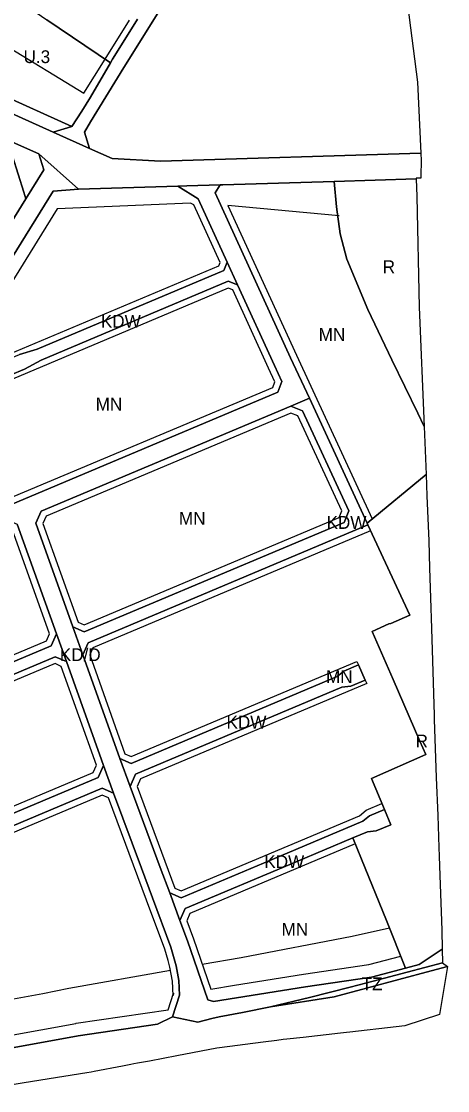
# Model space of a CAD drawing. Extents: x 7438199 to 7440548, y 5549253 to 5551017.
# Drawn here: x 7440215 to 7440548, y 5549426 to 5550261 of the extents above; entities that cross this region are included whole.
import ezdxf

# ---------------------------------------------------------------- set-up
doc = ezdxf.new("R2010")
doc.units = 0
for name, color, linetype in [('linie_rozgraniczajace', 7, 'Continuous'), ('linie_zabudowy_nieprzekraczalne', 7, 'Continuous'), ('oznaczenia_przeznaczen', 7, 'Continuous')]:
    doc.layers.add(name, color=color, linetype=linetype)

msp = doc.modelspace()

# ---------------------------------------------------------------- linework, layer by layer
at = {"layer": 'linie_rozgraniczajace'}
for points in [[(7440264.09, 5550174.87), (7440268.9, 5550182.89), (7440294.89, 5550225.52), (7440333.29, 5550286.98), (7440363.71, 5550335.92), (7440419.81, 5550425.76), (7440445, 5550466.09), (7440446.93, 5550470.08), (7440464.51, 5550499.53), (7440473.34, 5550465.22), (7440474.91, 5550458.79), (7440492.18, 5550389.39), (7440494, 5550382.09), (7440512.2, 5550309.41), (7440524.54, 5550213.92), (7440527.09, 5550158.4), (7440323.7, 5550152.27), (7440285.69, 5550154.28), (7440268.06, 5550162.2)], [(7440176.26, 5550285.71), (7440184.28, 5550297.74), (7440234.78, 5550262.81), (7440284.54, 5550229.12), (7440268.76, 5550202.14), (7440261.99, 5550191.28), (7440254.35, 5550179.32), (7440196.44, 5550205.34), (7440196.82, 5550220.59), (7440191.47, 5550241.49), (7440186.53, 5550255.03), (7440186.13, 5550256.24)], [(7439725.4, 5550171.35), (7440006.11, 5550230.82), (7440108.24, 5550249.01), (7440115.53, 5550250.21), (7440127.83, 5550252.14), (7440135.16, 5550252.88), (7440146.82, 5550253.26), (7440186.13, 5550256.24), (7440186.53, 5550255.03), (7440191.47, 5550241.49), (7440196.82, 5550220.59), (7440196.44, 5550205.34), (7440254.35, 5550179.32), (7440254.29, 5550179.23), (7440239.79, 5550174.9), (7440196.18, 5550194.5), (7440182.3, 5550200.05), (7440164.13, 5550206.11), (7440147.62, 5550209.57), (7440127.01, 5550211.36), (7440111.64, 5550210.92), (7440091.38, 5550208), (7439739.32, 5550133.41), (7439728.52, 5550141.21)], [(7439734.4, 5550101.63), (7439742.6, 5550113.67), (7440022.09, 5550172.88), (7440076.8, 5550177.8), (7440098.13, 5550180.68), (7440131.92, 5550186.14), (7440147.76, 5550189.01), (7440166.02, 5550184.48), (7440181.83, 5550178.47), (7440228.49, 5550158.06), (7440232.34, 5550145.46), (7440218.28, 5550122.77), (7440216.66, 5550128.03), (7440208.01, 5550156.1), (7440178.05, 5550169.21), (7440163.03, 5550174.92), (7440147.44, 5550178.79), (7440133.61, 5550176.28), (7440099.6, 5550170.79), (7440077.91, 5550167.86), (7440059.07, 5550166.16), (7440023.58, 5550162.97)], [(7440059.07, 5550166.16), (7440077.91, 5550167.86), (7440099.6, 5550170.79), (7440133.61, 5550176.28), (7440147.44, 5550178.79), (7440163.03, 5550174.92), (7440178.05, 5550169.21), (7440208.01, 5550156.1), (7440216.66, 5550128.03), (7440218.28, 5550122.77), (7440134.07, 5549986.87), (7440125.24, 5549987.71), (7440074.8, 5550123.91)], [(7440366.24, 5550127.47), (7440370.12, 5550133.66), (7440372.31, 5550133.73), (7440459.26, 5550136.35), (7440461.29, 5550116.56), (7440464.12, 5550095.35), (7440469.18, 5550075.52), (7440485.71, 5550036.16), (7440504.52, 5549996.98), (7440524.63, 5549955.12), (7440529.62, 5549944.7), (7440531.22, 5549907.17), (7440485.13, 5549869.19), (7440439.95, 5549966.81), (7440425.31, 5549998.44)], [(7440459.26, 5550136.35), (7440523.49, 5550138.28), (7440523.91, 5550124.53), (7440525.81, 5550038.1), (7440529.62, 5549944.7), (7440524.63, 5549955.12), (7440504.52, 5549996.98), (7440485.71, 5550036.16), (7440469.18, 5550075.52), (7440464.12, 5550095.35), (7440461.29, 5550116.56)], [(7440202.09, 5549996.27), (7440213.47, 5550001.07), (7440227.08, 5550005.17), (7440373.11, 5550066.69), (7440375.68, 5550073.21), (7440383.8, 5550055.48), (7440376.51, 5550058.35), (7440230.18, 5549996.72), (7440217.22, 5549989.63), (7440206.12, 5549984.95)], [(7440122.18, 5549849.49), (7440206.12, 5549984.95), (7440217.22, 5549989.63), (7440230.18, 5549996.72), (7440376.51, 5550058.35), (7440383.8, 5550055.48), (7440412.59, 5549992.59), (7440418.47, 5549979.89), (7440415.19, 5549971.57), (7440206.23, 5549883.55), (7440201.62, 5549881.61), (7440131.53, 5549852.08)], [(7440255.16, 5549788.05), (7440263.96, 5549784.18), (7440467.09, 5549869.75), (7440470.7, 5549878.94), (7440434.55, 5549957.04), (7440425.36, 5549960.67), (7440439.95, 5549966.81), (7440485.13, 5549869.19), (7440485.76, 5549867.84), (7440266.99, 5549775.69), (7440262.89, 5549766.38)], [(7440226.21, 5549869.19), (7440230.31, 5549878.5), (7440425.36, 5549960.67), (7440434.55, 5549957.04), (7440470.7, 5549878.94), (7440467.09, 5549869.75), (7440263.96, 5549784.18), (7440255.16, 5549788.05)], [(7440474, 5549623.1), (7440485.37, 5549627.89), (7440492.31, 5549628.65), (7440503.69, 5549633.44), (7440498.65, 5549645.42), (7440488.49, 5549669.59), (7440530.94, 5549688.31), (7440526.28, 5549698.87), (7440505.38, 5549746.97), (7440489.14, 5549784.52), (7440502.21, 5549790.56), (7440503.54, 5549790.88), (7440518.4, 5549797.32), (7440485.76, 5549867.84), (7440485.13, 5549869.19), (7440531.22, 5549907.17), (7440531.88, 5549890.64), (7440533.26, 5549855.38), (7440533.92, 5549834.1), (7440534.64, 5549810.86), (7440535.39, 5549786.74), (7440536.16, 5549761.55), (7440537.48, 5549719.16), (7440537.6, 5549715.71), (7440539.21, 5549670.4), (7440540.27, 5549640.79), (7440541.17, 5549615.61), (7440541.41, 5549608.95), (7440541.95, 5549593.74), (7440542.97, 5549565.26), (7440543.39, 5549551.01), (7440543.82, 5549536.27), (7440525.92, 5549524.28), (7440515.22, 5549521.41), (7440500.23, 5549558.55), (7440480.75, 5549606.49)], [(7440031.9, 5549698.99), (7440065.46, 5549752.89), (7440059.1, 5549767.45), (7440073.14, 5549774.28), (7440080.98, 5549777.82), (7440089.49, 5549781.67), (7440090.03, 5549782.03), (7440104.04, 5549788.87), (7440097.49, 5549804.44), (7440096.64, 5549806.47), (7440113.1, 5549832.93), (7440123.98, 5549837.51), (7440134.78, 5549843.69), (7440202.69, 5549872.29), (7440211.65, 5549868.35), (7440242.24, 5549782.61), (7440238.14, 5549773.3), (7440041.78, 5549690.58), (7440033.47, 5549694.77)], [(7440262.89, 5549766.38), (7440266.99, 5549775.69), (7440485.76, 5549867.84), (7440518.4, 5549797.32), (7440503.54, 5549790.88), (7440502.21, 5549790.56), (7440489.14, 5549784.52), (7440505.38, 5549746.97), (7440526.28, 5549698.87), (7440530.94, 5549688.31), (7440488.49, 5549669.59), (7440498.65, 5549645.42), (7440486.96, 5549640.49), (7440481.88, 5549636.19), (7440403.99, 5549603.37), (7440339.64, 5549576.27), (7440330.76, 5549580.12), (7440323.37, 5549600.1), (7440299.95, 5549663.42), (7440304.13, 5549673.07), (7440465.27, 5549740.94), (7440472.38, 5549741.72), (7440483.71, 5549746.49), (7440478.33, 5549758.38), (7440466.84, 5549753.54), (7440461.77, 5549749.24), (7440300.64, 5549681.36), (7440291.84, 5549685.24)], [(7440041.1, 5549674.34), (7440045.11, 5549682.22), (7440241.17, 5549764.81), (7440249.97, 5549760.93), (7440277.33, 5549684.23), (7440278.95, 5549679.86), (7440274.82, 5549670.48), (7440084.76, 5549590.42), (7440080.1, 5549588.46), (7440076.85, 5549590.1), (7440071.56, 5549592.77)], [(7440291.84, 5549685.24), (7440300.64, 5549681.36), (7440461.77, 5549749.24), (7440466.84, 5549753.54), (7440478.33, 5549758.38), (7440483.71, 5549746.49), (7440472.38, 5549741.72), (7440465.27, 5549740.94), (7440304.13, 5549673.07), (7440299.95, 5549663.42)], [(7440330.76, 5549580.12), (7440339.64, 5549576.27), (7440403.99, 5549603.37), (7440481.88, 5549636.19), (7440486.96, 5549640.49), (7440498.65, 5549645.42), (7440503.69, 5549633.44), (7440492.31, 5549628.65), (7440485.37, 5549627.89), (7440474, 5549623.1), (7440429.64, 5549604.42), (7440342.81, 5549567.84), (7440338.81, 5549558.56)], [(7440338.81, 5549558.56), (7440342.81, 5549567.84), (7440429.64, 5549604.42), (7440474, 5549623.1), (7440480.75, 5549606.49), (7440500.23, 5549558.55), (7440515.22, 5549521.41), (7440488.58, 5549514.29), (7440436.97, 5549506.74), (7440382.91, 5549498.03), (7440365.13, 5549495.17), (7440360.59, 5549496.57), (7440344.78, 5549542.56)], [(7440409.68, 5549491.08), (7440440.15, 5549498.28), (7440471.95, 5549506.37), (7440489.81, 5549511.12), (7440516.52, 5549518.21), (7440544.14, 5549525.54), (7440548.04, 5549522.56), (7440535.22, 5549519.17), (7440459.43, 5549498.82)]]:
    msp.add_lwpolyline(points, close=True, dxfattribs=at)
for points in [[(7440333.29, 5550286.98), (7440294.89, 5550225.52), (7440268.9, 5550182.89), (7440264.09, 5550174.87), (7440268.06, 5550162.2), (7440239.79, 5550174.9), (7440254.29, 5550179.23), (7440254.35, 5550179.32), (7440261.99, 5550191.28), (7440268.76, 5550202.14), (7440284.54, 5550229.12), (7440286.14, 5550231.84), (7440303.6, 5550259.85), (7440305.69, 5550263.33)], [(7440305.69, 5550263.33), (7440303.6, 5550259.85), (7440286.14, 5550231.84), (7440284.54, 5550229.12), (7440234.78, 5550262.81)], [(7439512.65, 5550106.55), (7439708.69, 5550128.79), (7439738.46, 5550133.23), (7439739.32, 5550133.41), (7440091.38, 5550208), (7440111.64, 5550210.92), (7440127.01, 5550211.36), (7440147.62, 5550209.57), (7440164.13, 5550206.11), (7440182.3, 5550200.05), (7440196.18, 5550194.5), (7440239.79, 5550174.9), (7440268.06, 5550162.2)], [(7440268.06, 5550162.2), (7440285.69, 5550154.28), (7440323.7, 5550152.27), (7440527.09, 5550158.4), (7440527.35, 5550152.82), (7440527.17, 5550140.63), (7440527.14, 5550138.97), (7440523.47, 5550138.88), (7440523.49, 5550138.28), (7440459.26, 5550136.35), (7440372.31, 5550133.73), (7440370.12, 5550133.66), (7440344.16, 5550132.88), (7440337.06, 5550132.67), (7440259.38, 5550130.33), (7440228.49, 5550158.06), (7440181.83, 5550178.47)], [(7440134.07, 5549986.87), (7440218.28, 5550122.77), (7440232.34, 5550145.46), (7440228.49, 5550158.06), (7440259.38, 5550130.33), (7440239.68, 5550128.82), (7440041.95, 5549809.72)], [(7440206.23, 5549883.55), (7440415.19, 5549971.57), (7440418.47, 5549979.89), (7440412.59, 5549992.59), (7440383.8, 5550055.48), (7440375.68, 5550073.21), (7440353.04, 5550122.65), (7440337.06, 5550132.67), (7440344.16, 5550132.88), (7440370.12, 5550133.66), (7440366.24, 5550127.47), (7440425.31, 5549998.44), (7440439.95, 5549966.81), (7440425.36, 5549960.67), (7440230.31, 5549878.5), (7440226.21, 5549869.19), (7440255.16, 5549788.05), (7440262.89, 5549766.38), (7440291.84, 5549685.24), (7440299.95, 5549663.42), (7440323.37, 5549600.1), (7440330.76, 5549580.12), (7440338.81, 5549558.56), (7440344.78, 5549542.56), (7440360.59, 5549496.57), (7440365.13, 5549495.17), (7440382.91, 5549498.03), (7440436.97, 5549506.74), (7440488.58, 5549514.29), (7440515.22, 5549521.41), (7440525.92, 5549524.28), (7440543.82, 5549536.27), (7440544.14, 5549525.54), (7440516.52, 5549518.21), (7440489.81, 5549511.12), (7440471.95, 5549506.37), (7440440.15, 5549498.28), (7440409.68, 5549491.08), (7440387.65, 5549486.73), (7440369.5, 5549483.14), (7440363.84, 5549482.02), (7440352.76, 5549478.99), (7440332.89, 5549483.38), (7440338.55, 5549500.21), (7440337.9, 5549511.74), (7440335.88, 5549523.1), (7440334.36, 5549528.67), (7440331.67, 5549537.67), (7440317.28, 5549576.21), (7440308.67, 5549599.51), (7440286.94, 5549658.24), (7440278.95, 5549679.86), (7440277.33, 5549684.23), (7440249.97, 5549760.93), (7440242.24, 5549782.61), (7440211.65, 5549868.35)], [(7440041.95, 5549809.72), (7440239.68, 5550128.82), (7440259.38, 5550130.33), (7440337.06, 5550132.67), (7440353.04, 5550122.65), (7440375.68, 5550073.21), (7440373.11, 5550066.69), (7440227.08, 5550005.17), (7440213.47, 5550001.07)], [(7440041.78, 5549690.58), (7440238.14, 5549773.3), (7440242.24, 5549782.61), (7440249.97, 5549760.93), (7440241.17, 5549764.81), (7440045.11, 5549682.22)], [(7440084.76, 5549590.42), (7440274.82, 5549670.48), (7440278.95, 5549679.86), (7440286.94, 5549658.24), (7440278.07, 5549662.09), (7440110.41, 5549591.46)], [(7440110.41, 5549591.46), (7440278.07, 5549662.09), (7440286.94, 5549658.24), (7440308.67, 5549599.51), (7440317.28, 5549576.21), (7440331.67, 5549537.67), (7440334.36, 5549528.67), (7440335.88, 5549523.1), (7440337.9, 5549511.74), (7440338.55, 5549500.21), (7440332.89, 5549483.38), (7440321.22, 5549477.48), (7440259.23, 5549468.33), (7440061.53, 5549432.46)], [(7440061.53, 5549432.46), (7440259.23, 5549468.33), (7440321.22, 5549477.48), (7440332.89, 5549483.38), (7440352.76, 5549478.99), (7440363.84, 5549482.02), (7440369.5, 5549483.14), (7440387.65, 5549486.73), (7440409.68, 5549491.08), (7440459.43, 5549498.82), (7440535.22, 5549519.17), (7440548.04, 5549522.56), (7440541.74, 5549485.15), (7440514.48, 5549476.19), (7440507.87, 5549475.46), (7440471.59, 5549471.37), (7440469.03, 5549471.09), (7440464.21, 5549470.54), (7440435.08, 5549467.21), (7440422.32, 5549465.75), (7440419.59, 5549465.44), (7440414.62, 5549464.87), (7440403.78, 5549463.45), (7440369.76, 5549459), (7440367.68, 5549458.73), (7440336.35, 5549452.77), (7440314.88, 5549448.7), (7440305.65, 5549446.94), (7440302.7, 5549446.39), (7440300.43, 5549445.96), (7440293.76, 5549444.69), (7440271.79, 5549440.53), (7440269.28, 5549440.04), (7440266.04, 5549439.43), (7440248.05, 5549436.54), (7440217.1, 5549431.57), (7440181.02, 5549425.58)]]:
    msp.add_lwpolyline(points, dxfattribs=at)
at = {"layer": 'linie_zabudowy_nieprzekraczalne'}
for points in [[(7440182.55, 5550295.15), (7440201.03, 5550244.45), (7440201.32, 5550243.34), (7440263.66, 5550205.25), (7440280.33, 5550231.97), (7440299.34, 5550262.45)], [(7440202.09, 5549996.27), (7440200.97, 5549999.6), (7440369.23, 5550070.48), (7440370.25, 5550073.06), (7440349.66, 5550118.04), (7440346.94, 5550119.43), (7440242.77, 5550114.82), (7440050.44, 5549804.44), (7440017.57, 5549751.65), (7440037.47, 5549698.35), (7440041.97, 5549696.09), (7440234.37, 5549777.13), (7440236.86, 5549782.8), (7440207.67, 5549864.64), (7440202.65, 5549866.85), (7440109.9, 5549827.78)], [(7440463.18, 5550109.6), (7440376.32, 5550117.46), (7440429.85, 5550000.53), (7440489.12, 5549872.48)], [(7440125.6, 5549855.01), (7440204.29, 5549888.16), (7440411.31, 5549975.36), (7440413.03, 5549979.73), (7440408.05, 5549990.5), (7440380.09, 5550051.57), (7440376.57, 5550052.95), (7440202.94, 5549979.81)], [(7440231.59, 5549869), (7440259.15, 5549791.76), (7440264.01, 5549789.62), (7440463.21, 5549873.53), (7440465.27, 5549878.78), (7440430.86, 5549953.12), (7440425.42, 5549955.27), (7440234.09, 5549874.67), (7440231.59, 5549869)], [(7440487.86, 5549863.3), (7440270.76, 5549771.85), (7440268.27, 5549766.18), (7440295.82, 5549688.94), (7440300.68, 5549686.8), (7440477.09, 5549761.12), (7440478.33, 5549758.38)], [(7440075.56, 5549596.35), (7440080.29, 5549593.96), (7440271.04, 5549674.32), (7440273.54, 5549679.99), (7440245.99, 5549757.23), (7440241.13, 5549759.37), (7440048.74, 5549678.33), (7440046.56, 5549674.03), (7440075.56, 5549596.35)], [(7440483.71, 5549746.49), (7440484.91, 5549743.79), (7440307.92, 5549669.24), (7440305.34, 5549663.28), (7440334.71, 5549583.85), (7440339.67, 5549581.7), (7440479.23, 5549640.5), (7440484.31, 5549644.8), (7440496.72, 5549650.03)], [(7440059.74, 5549442.3), (7440257.44, 5549478.17), (7440257.77, 5549478.23), (7440329.45, 5549488.8), (7440333.81, 5549501.8), (7440333.56, 5549499.93), (7440332.93, 5549511.16), (7440331, 5549522.01), (7440329.56, 5549527.3), (7440326.92, 5549536.07), (7440312.6, 5549574.46), (7440312.59, 5549574.48), (7440283, 5549654.5), (7440278.04, 5549656.65), (7439996.62, 5549538.1)], [(7440475.82, 5549618.44), (7440346.6, 5549564.01), (7440344.2, 5549558.43), (7440349.51, 5549544.19), (7440362.99, 5549504.95), (7440381.32, 5549507.9), (7440435.45, 5549516.62), (7440486.56, 5549524.1), (7440511.45, 5549530.76)], [(7440356.26, 5549524.54), (7440386.72, 5549529.59), (7440473.41, 5549546.22), (7440502.58, 5549552.72)], [(7439921.15, 5549448.36), (7439977.32, 5549458.54), (7440026.18, 5549467.58), (7440114.41, 5549482.29), (7440180.19, 5549492.99), (7440197.01, 5549495.27), (7440231.53, 5549501.54), (7440251.84, 5549505.69), (7440331.41, 5549519.67)]]:
    msp.add_lwpolyline(points, dxfattribs=at)

# ---------------------------------------------------------------- texts
at = {"layer": 'oznaczenia_przeznaczen'}
for s, p in [('U.3', (7440216.51, 5550228.89)), ('R', (7440497.29, 5550064.65)), ('KDW', (7440276.96, 5550022.06)), ('MN', (7440447.25, 5550011.74)), ('MN', (7440272.91, 5549957.26)), ('MN', (7440338.02, 5549867.97)), ('KDW', (7440453.39, 5549864.75)), ('KD/D', (7440244.86, 5549761.38)), ('MN', (7440452.99, 5549744.24)), ('KDW', (7440375.17, 5549708.63)), ('R', (7440523.01, 5549693.87)), ('KDW', (7440404.75, 5549599.58)), ('MN', (7440418.22, 5549546.72)), ('TZ', (7440480.77, 5549504.07))]:
    msp.add_text(s, height=10, dxfattribs=at).set_placement(p)

doc.saveas('drawing.dxf')
